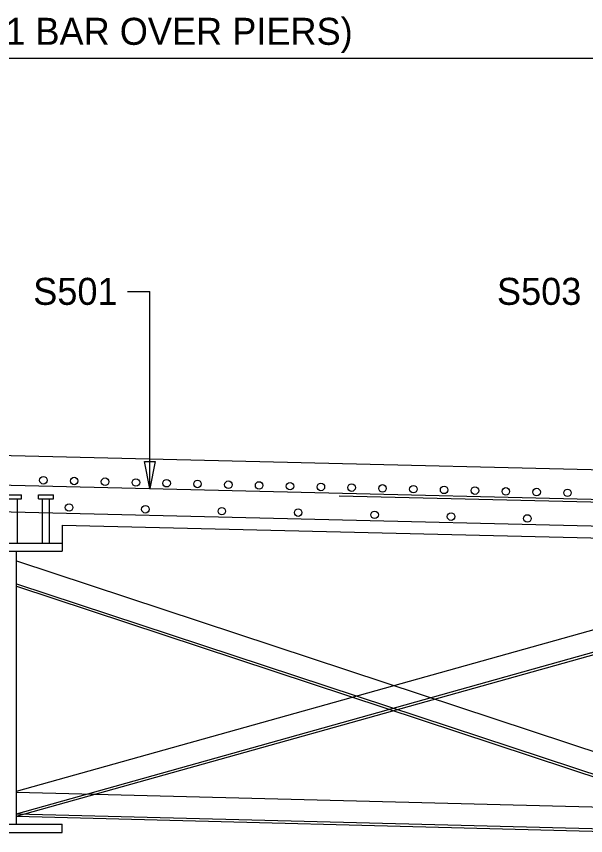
# Model space of a CAD drawing. Extents: x -86 to 68, y -5 to 62.
# Drawn here: x 45.75 to 51.65, y 22.9 to 31.39 of the extents above; entities that cross this region are included whole.
import ezdxf

# ---------------------------------------------------------------- set-up
doc = ezdxf.new("R2010")
doc.units = 0
for name, color, linetype in [('BR_P_Dia_Reinforcing', 7, 'Continuous'), ('BR_P_Gen_Text', 7, 'Continuous'), ('BR_P_Slab_Object', 7, 'Continuous'), ('BR_P_Slab_Reinforcing', 7, 'Continuous'), ('BR_X_Beam_Object', 7, 'Continuous'), ('TX_P_1', 7, 'Continuous'), ('TX_P_5', 7, 'Continuous')]:
    doc.layers.add(name, color=color, linetype=linetype)

msp = doc.modelspace()

# ---------------------------------------------------------------- linework, layer by layer
at = {"layer": 'BR_P_Dia_Reinforcing'}
for centre in [(46.6657, 26.5682), (47.624, 26.5452), (48.5823, 26.5222), (49.5407, 26.4992), (50.499, 26.4762), (51.4573, 26.4532), (46.2924, 26.3015), (47.084, 26.2825), (47.8757, 26.2635), (48.6671, 26.248), (49.459, 26.2255), (50.2507, 26.2065), (51.0424, 26.1875)]:
    msp.add_circle(centre, 0.039, dxfattribs=at)
at = {"layer": 'BR_P_Gen_Text'}
msp.add_lwpolyline([(47.0748, 26.7787), (47.1868, 26.7787), (47.1308, 26.4987)], close=True, dxfattribs=at)
at = {"layer": 'BR_P_Slab_Object'}
for p, q in [((12.499, 27.6356), (54.499, 26.6276)), ((46.221, 26.1179), (46.221, 25.9327)), ((46.221, 26.1179), (53.091, 25.9531))]:
    msp.add_line(p, q, dxfattribs=at)
at = {"layer": 'BR_P_Slab_Reinforcing'}
for p, q in [((34.2083, 26.8089), (54.1159, 26.3311)), ((34.0833, 26.5343), (54.3184, 26.0486)), ((49.091, 26.4209), (54.1159, 26.3003))]:
    msp.add_line(p, q, dxfattribs=at)
for centre in [(46.0272, 26.5835), (46.3458, 26.5759), (46.9856, 26.5605), (47.3041, 26.5529), (47.9439, 26.5375), (48.2624, 26.5299), (48.9022, 26.5145), (49.2208, 26.5069), (49.8606, 26.4915), (50.1791, 26.4839), (50.8189, 26.4685), (51.1374, 26.4609)]:
    msp.add_circle(centre, 0.039, dxfattribs=at)
at = {"layer": 'BR_X_Beam_Object'}
for p, q in [((45.221, 25.9327), (46.221, 25.9327)), ((46.221, 25.9327), (46.221, 25.8477)), ((45.221, 25.8477), (46.221, 25.8477)), ((45.7481, 23.0169), (45.7481, 25.8477)), ((45.7481, 25.7474), (53.5689, 23.1632)), ((45.7481, 23.3595), (53.5689, 25.5515)), ((45.7481, 25.5115), (53.5689, 22.9273)), ((45.7481, 25.4841), (53.5689, 22.8999)), ((45.7481, 23.1269), (53.5689, 25.3188)), ((45.7481, 23.0999), (53.5689, 25.2918)), ((45.7481, 23.35), (53.5689, 23.15)), ((45.7481, 23.1259), (53.5689, 22.9259)), ((45.7481, 23.0999), (53.5689, 22.8999)), ((45.221, 23.0169), (46.221, 23.0169)), ((46.221, 22.9319), (46.221, 23.0169)), ((45.221, 22.9319), (46.221, 22.9319))]:
    msp.add_line(p, q, dxfattribs=at)
at = {"layer": 'TX_P_1'}
for p, q in [((54.0124, 30.9573), (34.5272, 30.9573)), ((46.8997, 28.5418), (47.1308, 28.5418)), ((47.1308, 26.4987), (47.1308, 28.5418))]:
    msp.add_line(p, q, dxfattribs=at)
at = {"layer": 'TX_P_5'}
for p, q in [((45.643, 26.4327), (45.799, 26.4327)), ((45.799, 26.3907), (45.799, 26.4327)), ((45.9763, 26.4327), (46.1323, 26.4327)), ((45.9763, 26.3907), (45.9763, 26.4327)), ((46.1323, 26.3907), (46.1323, 26.4327)), ((45.643, 26.3907), (45.799, 26.3907)), ((45.757, 25.9327), (45.757, 26.3907)), ((45.9763, 26.3907), (46.1323, 26.3907)), ((46.0183, 25.9327), (46.0183, 26.3907)), ((46.0903, 25.9327), (46.0903, 26.3907))]:
    msp.add_line(p, q, dxfattribs=at)

# ---------------------------------------------------------------- texts
at = {"layer": 'TX_P_1'}
for s, p in [('42 - S507 (2 BETWEEN EACH S401 BAR OVER PIERS)', (39.7016, 31.0973)), ('S501', (45.9214, 28.4018)), ('S503', (50.7266, 28.4018))]:
    msp.add_text(s, height=0.28, dxfattribs=at).set_placement(p)

doc.saveas('drawing.dxf')
